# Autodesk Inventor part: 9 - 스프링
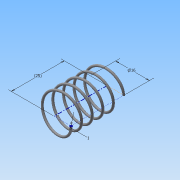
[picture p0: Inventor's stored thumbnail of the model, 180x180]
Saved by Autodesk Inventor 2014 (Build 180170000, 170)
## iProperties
Created: 2015-06
Part Number: 9 - 스프링
Material: 강철, 연강
Document SubType Name: Modeling
Designer: Administrator
Density: 7.86 g/cm^3
Appearance: 강철
Mass: 1.53479 g
Surface Area: 7.89194 cm^2
Volume: 0.195266 cm^3
Author: Administrator
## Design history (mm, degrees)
sketch "스케치1"
  geometry: L1 (0, 0)-(8, 0); L2 (8, 0)-(8, 21.5); L3 (8, 21.5)-(0, 21.5); L4 (0, 21.5)-(0, 0); C1 r 0.5 at (8, 0)
  constraints: 8 end point, 2 parallel, 1 centre point, 1 coincident, 1 horizontal, 1 perpendicular
  dimensions: "d0" = 21.5 distance between parallel lines of L1 L3 (derived); "d1" = 16 diameter of L2 L4; "d2" = 1 diameter of C1
feature "코일1" sketch "스케치1" pitch "d3" = 10; turns "d5" = 5; dims "d4" = 21.5 (= d0), "d6" = 0, angle "d7" = 90 deg, angle "d8" = 90 deg, "d9" = 0, "d10" = 0
node "작업 평면1"
sketch "스케치2"
  geometry: L1 (-8.5, 0)-(-7.5, 0) reference; 1 further point
  constraints: 1 horizontal alignment
extrude "돌출1" cut sketch "스케치2" distance "d12" = 10; taper "d13" = 0 deg
node "작업 평면2"
sketch "스케치3"
  geometry: L1 (-7.5, 0)-(-8.5, 0) reference; 1 further point
  constraints: 1 horizontal alignment
extrude "돌출2" cut sketch "스케치3" stored distance "d15" = 10; taper "d16" = 0 deg
node "솔리드1"
node "절단 모서리 투영1"
node "절단 모서리 투영2"
other parameters: "d11" = 0, "d14" = 21.5 (= d0)
